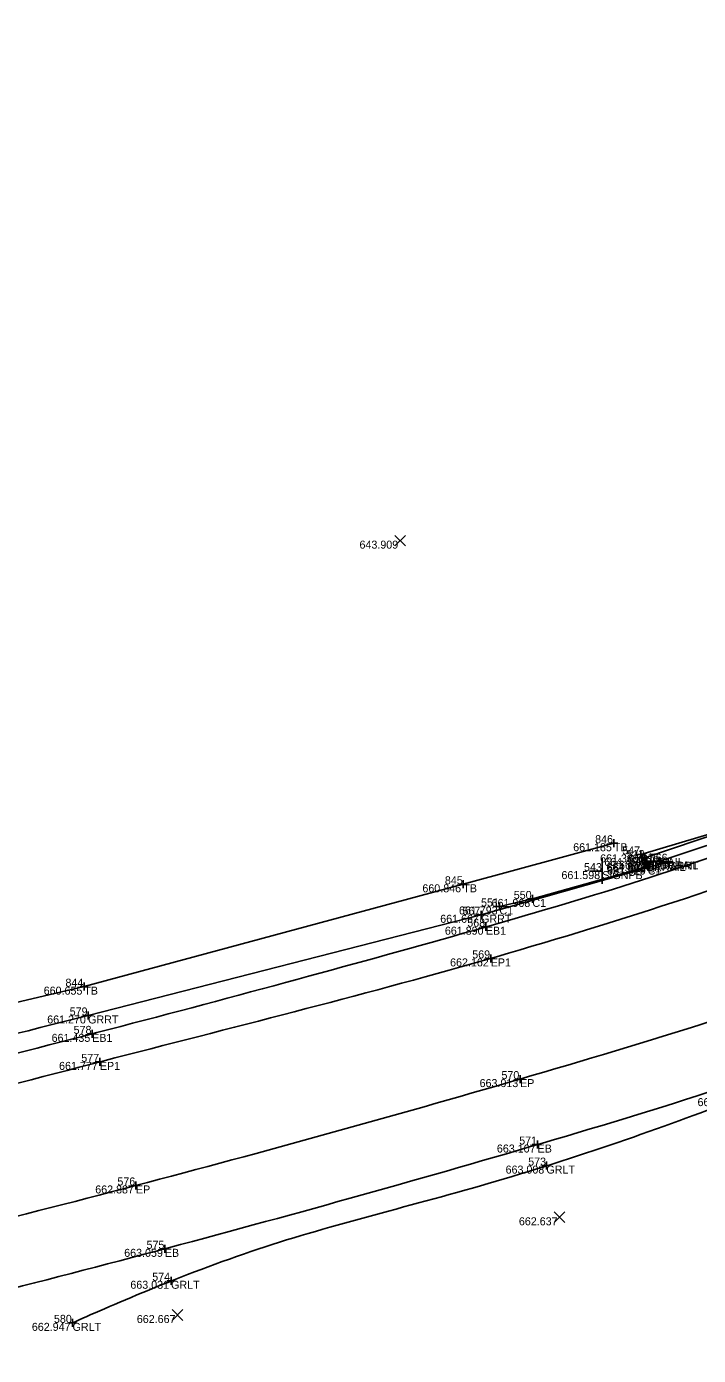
# Model space of a CAD drawing. Extents: x 2197382 to 2204062, y 634117 to 636522.
# Drawn here: x 2202277.4 to 2202361.4, y 635145.7 to 635311.8 of the extents above; entities that cross this region are included whole.
import ezdxf

# ---------------------------------------------------------------- set-up
doc = ezdxf.new("R2010")
doc.units = 0
for name, color, linetype in [('_CIVIL_CONSTRUCTION', 7, 'Continuous'), ('BR_X_SV_Rail', 7, 'Continuous'), ('GE_P_Alignment_100_Distances', 7, 'Continuous'), ('GE_P_Alignment_100_Stations', 7, 'Continuous'), ('GE_X_Alignment', 7, 'Continuous'), ('PF_P_Grade_Line', 7, 'Continuous'), ('PF_X_Ground_Line', 7, 'Continuous'), ('PV_X_Curb', 7, 'Continuous'), ('RD_X_GR_Rt', 7, 'Continuous'), ('RW_X_CL_100_Curve_Data', 7, 'Continuous'), ('RW_X_CL_100_Stations', 7, 'Continuous'), ('SH_Border', 7, 'Continuous'), ('SH_Cut_Line', 7, 'Continuous'), ('SH_Data', 7, 'Continuous'), ('SH_Text', 7, 'Continuous')]:
    doc.layers.add(name, color=color, linetype=linetype)

msp = doc.modelspace()

# ---------------------------------------------------------------- linework, layer by layer
at = {"layer": '_CIVIL_CONSTRUCTION'}
for p, q in [((2202350.79, 635210.22), (2202350.79, 635209.22)), ((2202350.29, 635209.72), (2202351.29, 635209.72)), ((2202350.79, 635209.72), (2202350.79, 635209.72)), ((2202353.67, 635208.33), (2202354.67, 635208.33)), ((2202354.17, 635208.83), (2202354.17, 635207.83)), ((2202354.17, 635208.33), (2202354.17, 635208.33)), ((2202354.69, 635208.38), (2202354.69, 635207.38)), ((2202354.19, 635207.88), (2202355.19, 635207.88)), ((2202354.43, 635207.25), (2202355.43, 635207.25)), ((2202354.54, 635206.8), (2202355.54, 635206.8)), ((2202354.56, 635207.07), (2202355.56, 635207.07)), ((2202354.69, 635207.88), (2202354.69, 635207.88)), ((2202354.93, 635207.75), (2202354.93, 635206.75)), ((2202354.93, 635207.25), (2202354.93, 635207.25)), ((2202355.04, 635207.3), (2202355.04, 635206.3)), ((2202355.04, 635206.8), (2202355.04, 635206.8)), ((2202355.06, 635207.57), (2202355.06, 635206.57)), ((2202355.06, 635207.07), (2202355.06, 635207.07)), ((2202356.05, 635207.47), (2202357.05, 635207.47)), ((2202356.55, 635207.97), (2202356.55, 635206.97)), ((2202356.55, 635207.47), (2202356.55, 635207.47)), ((2202357.1, 635207.41), (2202358.1, 635207.41)), ((2202357.6, 635207.91), (2202357.6, 635206.91)), ((2202357.6, 635207.41), (2202357.6, 635207.41)), ((2202331.98, 635205.09), (2202331.98, 635204.09)), ((2202331.48, 635204.59), (2202332.48, 635204.59)), ((2202331.98, 635204.59), (2202331.98, 635204.59)), ((2202336, 635201.82), (2202337, 635201.82)), ((2202336.5, 635202.32), (2202336.5, 635201.32)), ((2202336.5, 635201.82), (2202336.5, 635201.82)), ((2202340.12, 635202.76), (2202341.12, 635202.76)), ((2202340.62, 635203.26), (2202340.62, 635202.26)), ((2202340.62, 635202.76), (2202340.62, 635202.76)), ((2202333.7, 635200.78), (2202334.7, 635200.78)), ((2202334.2, 635201.28), (2202334.2, 635200.28)), ((2202334.2, 635200.78), (2202334.2, 635200.78)), ((2202334.3, 635199.29), (2202335.3, 635199.29)), ((2202334.8, 635199.79), (2202334.8, 635198.79)), ((2202334.8, 635199.29), (2202334.8, 635199.29)), ((2202334.91, 635195.33), (2202335.91, 635195.33)), ((2202335.41, 635195.83), (2202335.41, 635194.83)), ((2202335.41, 635195.33), (2202335.41, 635195.33)), ((2202284.11, 635191.8), (2202285.11, 635191.8)), ((2202284.61, 635192.3), (2202284.61, 635191.3)), ((2202284.61, 635191.8), (2202284.61, 635191.8)), ((2202285.09, 635188.7), (2202285.09, 635187.7)), ((2202284.59, 635188.2), (2202285.59, 635188.2)), ((2202285.09, 635188.2), (2202285.09, 635188.2)), ((2202285.1, 635185.9), (2202286.1, 635185.9)), ((2202285.6, 635186.4), (2202285.6, 635185.4)), ((2202285.6, 635185.9), (2202285.6, 635185.9)), ((2202286.06, 635182.4), (2202287.06, 635182.4)), ((2202286.56, 635182.9), (2202286.56, 635181.9)), ((2202286.56, 635182.4), (2202286.56, 635182.4)), ((2202338.58, 635180.25), (2202339.58, 635180.25)), ((2202339.08, 635180.75), (2202339.08, 635179.75)), ((2202339.08, 635180.25), (2202339.08, 635180.25)), ((2202340.77, 635172.07), (2202341.77, 635172.07)), ((2202341.27, 635172.57), (2202341.27, 635171.57)), ((2202341.27, 635172.07), (2202341.27, 635172.07)), ((2202341.87, 635169.44), (2202342.87, 635169.44)), ((2202342.37, 635169.94), (2202342.37, 635168.94)), ((2202342.37, 635169.44), (2202342.37, 635169.44)), ((2202290.57, 635166.96), (2202291.57, 635166.96)), ((2202291.07, 635167.46), (2202291.07, 635166.46)), ((2202291.07, 635166.96), (2202291.07, 635166.96)), ((2202294.18, 635159.04), (2202295.18, 635159.04)), ((2202294.68, 635159.54), (2202294.68, 635158.54)), ((2202294.68, 635159.04), (2202294.68, 635159.04)), ((2202295.46, 635155.55), (2202295.46, 635154.55)), ((2202294.96, 635155.05), (2202295.96, 635155.05)), ((2202295.46, 635155.05), (2202295.46, 635155.05)), ((2202283.15, 635150.29), (2202283.15, 635149.29)), ((2202282.65, 635149.79), (2202283.65, 635149.79)), ((2202283.15, 635149.79), (2202283.15, 635149.79))]:
    msp.add_line(p, q, dxfattribs=at)
at = {"layer": 'BR_X_SV_Rail'}
msp.add_lwpolyline([(2202354.69, 635207.88), (2202367.86, 635212.37), (2202368.19, 635211.35), (2202356.55, 635207.47), (2202354.93, 635207.25)], close=True, dxfattribs=at)
at = {"layer": 'GE_P_Alignment_100_Distances'}
for points in [[(2202381.16, 635210.32), (2202366.1, 635204.72), (2202334.8, 635194.56), (2202286.96, 635182.66), (2202239.06, 635169.83), (2202190.57, 635161.31), (2202142.09, 635153.59), (2202092.91, 635148.21), (2202043.66, 635145.11), (2201994.31, 635143.9), (2201945.2, 635145.32), (2201896.27, 635148.27), (2201847.56, 635154.73), (2201798.82, 635161.43), (2201750.63, 635171.43), (2201702.91, 635182.55), (2201655.93, 635196.35), (2201609.49, 635212.58), (2201563.54, 635230.53), (2201517.8, 635250.11), (2201472.75, 635271.46), (2201426.49, 635290.37), (2201396.61, 635304.57), (2201381.57, 635311.27)], [(2202386.45, 635195.59), (2202370.91, 635189.75), (2202339.13, 635180.04), (2202291.09, 635166.72), (2202242.56, 635154.7), (2202193.6, 635144.9), (2202144.21, 635137.83), (2202094.71, 635131.91), (2202044.78, 635129.37), (2201994.9, 635127.35), (2201945.05, 635129.12), (2201895.29, 635131.98), (2201845.71, 635138.04), (2201796.31, 635145.15), (2201747.25, 635154.67), (2201698.84, 635166.79), (2201650.88, 635180.71), (2201603.87, 635197.49), (2201557.29, 635215.61), (2201511.45, 635235.48), (2201465.51, 635255.02), (2201420.2, 635275.98), (2201389.78, 635289.5), (2201374.58, 635296.3)]]:
    msp.add_open_spline(points, degree=3, dxfattribs=at)
at = {"layer": 'GE_P_Alignment_100_Stations'}
for p, q in [((2202349.35, 635207.84), (2202349.35, 635204.64)), ((2202349.35, 635206.24), (2202347.75, 635206.24))]:
    msp.add_line(p, q, dxfattribs=at)
at = {"layer": 'GE_X_Alignment'}
for points in [[(2202397.01, 635220.75), (2202390.94, 635219.55), (2202370.91, 635209.9), (2202333.66, 635198.74), (2202286.3, 635185.91), (2202238.23, 635173.94), (2202190.11, 635164.74), (2202141.77, 635157.37), (2202092.76, 635151.86), (2202043.46, 635148.8), (2201994.27, 635147.52), (2201945.31, 635148.99), (2201896.77, 635151.89), (2201848.09, 635157.45), (2201799.55, 635164.97), (2201751.45, 635174.5), (2201703.93, 635186.11), (2201657.05, 635199.39), (2201610.65, 635215.73), (2201564.74, 635233.57), (2201519.24, 635253.33), (2201473.99, 635273.72), (2201428.46, 635294.12), (2201398.16, 635307.71), (2201382.96, 635314.43)], [(2202389.25, 635188.21), (2202373.6, 635181.86), (2202342.05, 635172.03), (2202293.67, 635158.58), (2202244.91, 635146.21), (2202194.94, 635137.22), (2202145.31, 635129.1), (2202095.52, 635123.76), (2202045.13, 635120.93), (2201994.93, 635119.27), (2201944.5, 635120.71), (2201894.53, 635123.86), (2201844.41, 635129.5), (2201794.77, 635136.96), (2201745.53, 635147.41), (2201696.65, 635158.71), (2201648.35, 635173.37), (2201600.81, 635189.62), (2201553.51, 635207.06), (2201508.05, 635227.84), (2201462.09, 635247.86), (2201416.63, 635268.36), (2201386.21, 635281.9), (2201371.14, 635288.76)], [(2202540.06, 635152.93), (2202529.43, 635144.25), (2202507.23, 635123.46), (2202471.72, 635092.05), (2202435.62, 635056.76), (2202402.1, 635018.87), (2202368.73, 634981.48), (2202336.15, 634943.25), (2202304.62, 634904.21), (2202274.11, 634864.33), (2202244.37, 634823.83), (2202215.65, 634782.83), (2202187.65, 634741.05), (2202161.54, 634698.56), (2202134.84, 634656), (2202111.41, 634611.66), (2202087.71, 634567.52), (2202064.97, 634523.35), (2202044.2, 634477.97), (2202023.42, 634432.25), (2202003.66, 634386.18), (2201990.91, 634355.55), (2201984.79, 634340.33)]]:
    msp.add_open_spline(points, degree=3, dxfattribs=at)
at = {"layer": 'PF_P_Grade_Line'}
msp.add_lwpolyline([(2202091.81, 635154.11), (2202139.77, 635160.01), (2202166.7, 635170.29), (2202188.71, 635175.49), (2202236.77, 635180.56), (2202284.61, 635191.8), (2202331.98, 635204.59), (2202350.79, 635209.72)], dxfattribs=at)
at = {"layer": 'PF_X_Ground_Line'}
msp.add_open_spline([(2202366.36, 635177.87), (2202358.49, 635174.71), (2202335.02, 635166.55), (2202306.3, 635159.99), (2202287.22, 635151.64), (2202283.15, 635149.79)], degree=3, dxfattribs=at)
at = {"layer": 'PV_X_Curb'}
msp.add_lwpolyline([(2202355.04, 635206.8), (2202340.62, 635202.76), (2202336.5, 635201.82)], dxfattribs=at)
at = {"layer": 'RD_X_GR_Rt'}
for p, q in [((2202357.6, 635207.41), (2202334.2, 635200.78)), ((2202334.2, 635200.78), (2202285.09, 635188.2))]:
    msp.add_line(p, q, dxfattribs=at)
msp.add_open_spline([(2202285.09, 635188.2), (2202269.08, 635184.09), (2202237.52, 635176.57), (2202198.5, 635167.9), (2202175.29, 635167.41), (2202168.09, 635167.52)], degree=3, dxfattribs=at)
at = {"layer": 'RW_X_CL_100_Curve_Data'}
for p, q in [((2202323.43, 635246.86), (2202324.76, 635248.19)), ((2202323.43, 635248.19), (2202324.76, 635246.86)), ((2202343.36, 635162.31), (2202344.69, 635163.65)), ((2202343.36, 635163.65), (2202344.69, 635162.31)), ((2202295.61, 635150.1), (2202296.94, 635151.44)), ((2202295.61, 635151.44), (2202296.94, 635150.1))]:
    msp.add_line(p, q, dxfattribs=at)
at = {"layer": 'SH_Text'}
msp.add_lwpolyline([(2202396.57, 635222.37), (2202383.18, 635217.72), (2202367.99, 635212.44), (2202354.17, 635208.33), (2202355.06, 635207.07)], dxfattribs=at)

# ---------------------------------------------------------------- texts
at = {"layer": 'RW_X_CL_100_Stations'}
for s, p in [('512', (2202352.4, 635207.88)), ('515', (2202354.26, 635207.47)), ('664.457', (2202349.6, 635206.88)), ('664.542', (2202349.86, 635206.25)), ('664.570', (2202351.44, 635206.47)), ('516', (2202352.61, 635207.25)), ('BRRAIL', (2202354.69, 635206.88)), ('BRRAIL', (2202354.93, 635206.25)), ('BRRAIL', (2202356.55, 635206.47))]:
    msp.add_text(s, height=1, dxfattribs=at).set_placement(p)
at = {"layer": 'SH_Border'}
for s, p in [('TB', (2202350.79, 635208.72)), ('B1', (2202354.17, 635207.33)), ('C1', (2202355.04, 635205.8)), ('B1', (2202355.06, 635206.07)), ('GRRT', (2202357.6, 635206.41)), ('SIGNPB', (2202349.35, 635205.24)), ('TB', (2202331.98, 635203.59)), ('C1', (2202336.5, 635200.82)), ('C1', (2202340.62, 635201.76)), ('GRRT', (2202334.2, 635199.78)), ('EB1', (2202334.8, 635198.29)), ('EP1', (2202335.41, 635194.33)), ('TB', (2202284.61, 635190.8)), ('GRRT', (2202285.09, 635187.2)), ('EB1', (2202285.6, 635184.9)), ('EP1', (2202286.56, 635181.4)), ('EP', (2202339.08, 635179.25)), ('EB', (2202341.27, 635171.07)), ('GRLT', (2202342.37, 635168.44)), ('EP', (2202291.07, 635165.96)), ('EB', (2202294.68, 635158.04)), ('GRLT', (2202295.46, 635154.05)), ('GRLT', (2202283.15, 635148.79))]:
    msp.add_text(s, height=1, dxfattribs=at).set_placement(p)
at = {"layer": 'SH_Cut_Line'}
for s, p in [('846', (2202348.46, 635209.72)), ('547', (2202351.85, 635208.33)), ('566', (2202355.28, 635207.41)), ('543', (2202347.07, 635206.24)), ('548', (2202352.74, 635207.07)), ('549', (2202352.73, 635206.8)), ('845', (2202329.68, 635204.59)), ('550', (2202338.29, 635202.76)), ('567', (2202331.88, 635200.78)), ('551', (2202334.2, 635201.82)), ('568', (2202332.48, 635199.29)), ('569', (2202333.1, 635195.33)), ('844', (2202282.26, 635191.8)), ('579', (2202282.79, 635188.2)), ('578', (2202283.28, 635185.9)), ('577', (2202284.24, 635182.4)), ('570', (2202336.75, 635180.25)), ('571', (2202338.97, 635172.07)), ('573', (2202340.09, 635169.44)), ('576', (2202288.75, 635166.96)), ('575', (2202292.39, 635159.04)), ('574', (2202293.11, 635155.05)), ('580', (2202280.82, 635149.79))]:
    msp.add_text(s, height=1, dxfattribs=at).set_placement(p)
at = {"layer": 'SH_Data'}
for s, p in [('643.909', (2202319.01, 635246.53)), ('661.185', (2202345.72, 635208.72)), ('661.369', (2202349.08, 635207.33)), ('661.806', (2202349.96, 635206.07)), ('661.929', (2202349.95, 635205.8)), ('661.950', (2202352.49, 635206.41)), ('661.598', (2202344.25, 635205.24)), ('660.846', (2202326.87, 635203.59)), ('661.793', (2202331.44, 635200.82)), ('661.968', (2202335.52, 635201.76)), ('661.667', (2202329.1, 635199.78)), ('661.890', (2202329.68, 635198.29)), ('662.162', (2202330.33, 635194.33)), ('660.655', (2202279.54, 635190.8)), ('661.270', (2202279.98, 635187.2)), ('661.435', (2202280.53, 635184.9)), ('661.777', (2202281.46, 635181.4)), ('663.013', (2202334.02, 635179.25)), ('663.048', (2202361.26, 635176.87)), ('663.107', (2202336.18, 635171.07)), ('663.008', (2202337.27, 635168.44)), ('662.887', (2202285.98, 635165.96)), ('662.637', (2202338.93, 635161.98)), ('663.059', (2202289.6, 635158.04)), ('663.031', (2202290.37, 635154.05)), ('662.667', (2202291.18, 635149.77)), ('662.947', (2202278.06, 635148.79))]:
    msp.add_text(s, height=1, dxfattribs=at).set_placement(p)

doc.saveas('drawing.dxf')
